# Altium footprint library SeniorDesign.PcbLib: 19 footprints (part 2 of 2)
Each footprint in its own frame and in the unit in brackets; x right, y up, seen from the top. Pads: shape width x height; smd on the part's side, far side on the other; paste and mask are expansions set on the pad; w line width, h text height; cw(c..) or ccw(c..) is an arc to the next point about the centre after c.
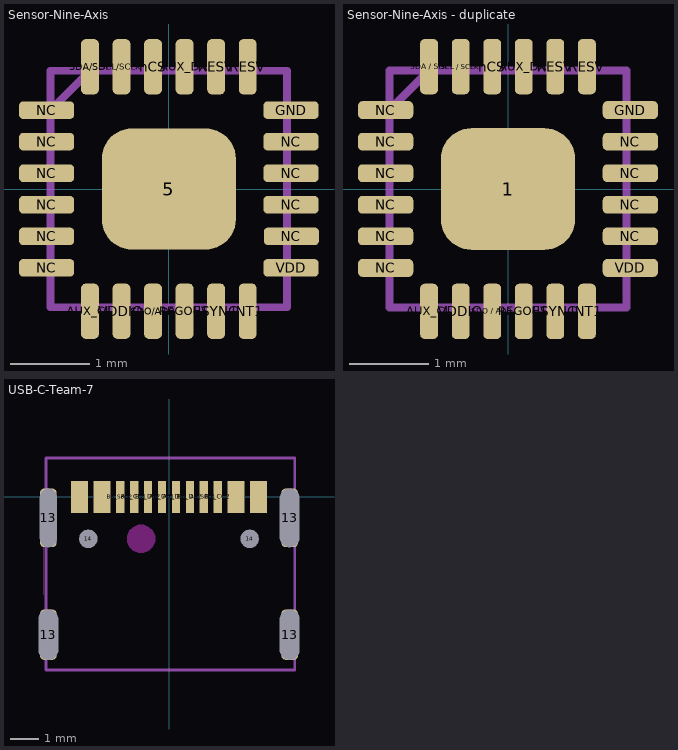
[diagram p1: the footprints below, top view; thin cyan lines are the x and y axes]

## Sensor-Nine-Axis [mm]
height 1
pads (26):
  rrect50% 1.7x1.54 smd: 5(0,0) ""(0,0)
  rrect50% 0.225x0.7 smd: AUX_CL(-1,-1.55) AUX_DA(0.2,1.55) FSYNC(0.6,-1.55) INT1(1,-1.55) nCS(-0.2,1.55) REGOUT(0.2,-1.55) RESV(0.6,1.55) RESV(1,1.55) SCL/SCLK(-0.6,1.55) SDA/SDI(-1,1.55) SDO/AD0(-0.2,-1.55) VDDIO(-0.6,-1.55)
  rrect50% 0.7x0.225 smd: GND(1.55,1) NC(-1.55,-1) NC(-1.55,-0.6) NC(-1.55,-0.2) NC(-1.55,0.2) NC(-1.55,0.6) NC(-1.55,1) NC(1.55,-0.2) NC(1.55,0.2) NC(1.55,0.6) NC(1.555,-0.6) VDD(1.55,-1)
Top Assembly:
  lines w0.1: -1.5,1 -1,1.5 ; -1.5,-1.5 -1.5,1.5 1.5,1.5 1.5,-1.5 -1.5,-1.5
  text ".Designator" at -0.9,-0.267 h0.4
3D body: height 1, standoff 0, extent -1.5,-1.5 1.5,1.5

## Sensor-Nine-Axis - duplicate [mm]
height 1
pads (25):
  rrect50% 1.7x1.54 smd: 1(0,0)
  rrect50% 0.225x0.7 smd: AUX_CL(-1,-1.55) AUX_DA(0.2,1.55) FSYNC(0.6,-1.55) INT1(1,-1.55) nCS(-0.2,1.55) REGOUT(0.2,-1.55) RESV(0.6,1.55) RESV(1,1.55) "SCL / SCLK"(-0.6,1.55) "SDA / SDI"(-1,1.55) "SDO / AD0"(-0.2,-1.55) VDDIO(-0.6,-1.55)
  rrect50% 0.7x0.225 smd: GND(1.55,1) NC(-1.55,-1) NC(-1.55,-0.6) NC(-1.55,-0.2) NC(-1.55,0.2) NC(-1.55,0.6) NC(-1.55,1) NC(1.55,-0.6) NC(1.55,-0.2) NC(1.55,0.2) NC(1.55,0.6) VDD(1.55,-1)
Top Assembly:
  lines w0.1: -1.5,1 -1,1.5 ; -1.5,-1.5 -1.5,1.5 1.5,1.5 1.5,-1.5 -1.5,-1.5
  text ".Designator" at -2.125,-2.45 h0.4
3D body: height 0.25, standoff 0, extent -1.5,-1.5 1.5,1.5

## USB-C-Team-7 [mm]
pads (18):
  rrect50% 0.6x1.8 hole 0.7 slot 1.8 at 90 deg mask+0: 13(-4.32,-4.93) 13(4.32,-4.93)
  rrect50% 0.6x2.1 hole 0.6 slot 2.1 at 90 deg mask+0: 13(-4.32,-0.75)
  rrect50% 0.6x2.1 hole 0.7 slot 2.1 at 90 deg mask+0: 13(4.32,-0.75)
  round 0.325 hole 0.65 mask+0: 14(-2.89,-1.5) 14(2.89,-1.5)
  rect 0.6x1.14 smd: A1_B12_GND(-3.2,0) A4_B9_VBUS(-2.4,0) B1_A12_GND(3.2,0) B4_A9_VBUS(2.4,0)
  rect 0.3x1.14 smd: A5_CC1(-1.25,0) A6_Dp1(-0.25,0) A7_Dn1(0.25,0) A8_SBU1(1.25,0) B5_CC2(1.75,0) B6_Dp2(0.75,0) B6_SBU2(-1.75,0) B7_Dn2(-0.75,0)
Keep-Out Layer:
  region: -1.5,-1.5 -1.5,-1.599 -1.424,-1.783 -1.283,-1.924 -1.099,-2 -1,-2 -0.901,-2 -0.717,-1.924 -0.576,-1.783 -0.5,-1.599 -0.5,-1.5 -0.5,-1.401 -0.576,-1.217 -0.717,-1.076 -0.901,-1 -1,-1 -1.099,-1 -1.283,-1.076 -1.424,-1.217 -1.5,-1.401
Top Assembly:
  pour cut-out: -4.5,-1.5 -4.5,-2.25 -4.5,-3.5
  lines w0.1: -4.4,-6.2 4.5,-6.2 4.5,1.4 -4.4,1.4 -4.4,-6.2
  text ".Designator" at -2.1,-3.467 h0.4
3D body "COM-15111--3DModel-STEP-56544.STEP": height 3.28, standoff -0.88, extent -4.42,-7.8 4.52,-0.2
